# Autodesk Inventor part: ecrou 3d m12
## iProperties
Author: ajt
Created: 2001-10
Part Number: ecrou 3d m12
Material: Par défaut
Document SubType Name: Proxy Part
Designer: ajt
Control State: 0
Master: False
Checked Out: False
PropertySet Name: Design Tracking Control
Shininess: 21.0
PropertySet Name: _Private Model Information
Length Units: 11269
Angle Units: 11283
Time Units: 11279
Mass Units: 11290
Length Display Precision: 3
Angle Display Precision: 2
Compacted: False
Density: 0.0
Volumn: 0.0
Area: 0.0
PropertySet Name: Model Information
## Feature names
1. LinkedPart1
